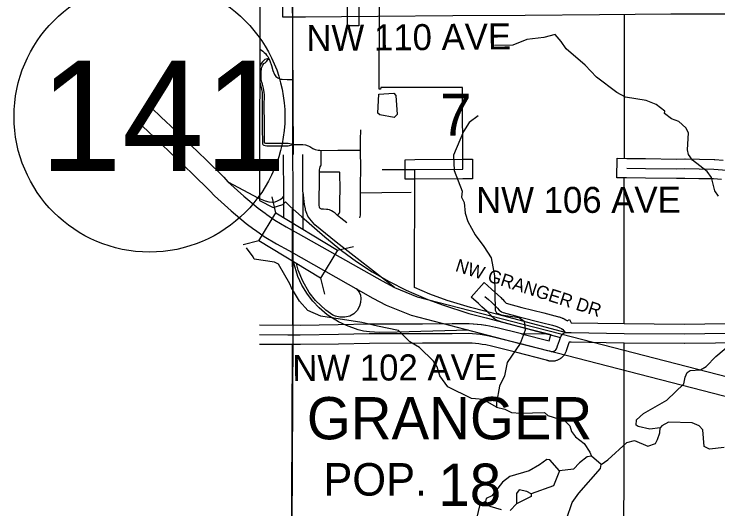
# Model space of a CAD drawing. Extents: x -1403959 to 81668, y -1400582 to 11018.
# Drawn here: x 6135.6 to 6345.3, y 9255.5 to 9402.8 of the extents above; entities that cross this region are included whole.
import ezdxf

# ---------------------------------------------------------------- set-up
doc = ezdxf.new("R2010")
doc.units = 0
for name, color, linetype in [('tdCiCityStreetTxt', 7, 'Continuous'), ('tdCiCoBndryTxt', 7, 'Continuous'), ('tdCiCorpBndryTxt', 7, 'Continuous'), ('tdCiMapCityName', 7, 'Continuous'), ('tdCiMapFrame', 7, 'Continuous'), ('tdCiRRCL', 7, 'Continuous'), ('tdCiSectLine', 7, 'Continuous'), ('tdCiSectTwpRng', 7, 'Continuous'), ('tdCoCityStreetMajor', 7, 'Continuous'), ('tdCoCityStreetMinor', 7, 'Continuous'), ('tdCoClipBndry', 7, 'Continuous'), ('tdCoDivCarto', 7, 'Continuous'), ('tdCoIntCL', 7, 'Continuous'), ('tdCoSecRteCL', 7, 'Continuous'), ('tdCoSectLinePart', 7, 'Continuous'), ('tdCoSectNmbr', 7, 'Continuous'), ('tdCoShieldCoRte', 7, 'Continuous'), ('tdCoShieldCoRteHrd', 7, 'Continuous'), ('tdCoSurfAsphalt', 7, 'Continuous'), ('tdCoSurfBitum', 7, 'Continuous')]:
    doc.layers.add(name, color=color, linetype=linetype)

msp = doc.modelspace()

# ---------------------------------------------------------------- linework, layer by layer
at = {"layer": 'tdCiCityStreetTxt'}
for p, q in [((6213.62, 9343.61), (6212.46, 9348.35)), ((6208.57, 9335.28), (6213.62, 9343.61)), ((6213.62, 9343.61), (6231.96, 9332.49)), ((6208.57, 9335.28), (6203.84, 9334.12)), ((6226.91, 9324.16), (6208.57, 9335.28)), ((6208.57, 9335.28), (6208.57, 9335.28)), ((6231.96, 9332.49), (6236.7, 9333.65)), ((6231.96, 9332.49), (6226.91, 9324.16)), ((6226.91, 9324.16), (6228.07, 9319.42))]:
    msp.add_line(p, q, dxfattribs=at)
at = {"layer": 'tdCiCoBndryTxt'}
for points in [[(6339.67, 9356.69), (6339.67, 9356.69), (6344.07, 9356.61), (6346.6, 9356.39), (6349.31, 9356.23), (6354.12, 9356.2), (6362.21, 9356.1), (6365.11, 9356.29), (6365.94, 9356.34)], [(6298.4, 9306.53), (6298.56, 9306.95), (6299.06, 9307.64), (6299.74, 9307.97)], [(6299.74, 9307.97), (6301.59, 9308.02), (6317.33, 9307.76), (6335.22, 9307.64), (6353.75, 9307.88), (6365.08, 9307.76), (6365.85, 9307.83)], [(6297.78, 9304.85), (6298.05, 9305.63), (6298.4, 9306.53)]]:
    msp.add_lwpolyline(points, dxfattribs=at)
at = {"layer": 'tdCiCorpBndryTxt'}
msp.add_lwpolyline([(6280.8, 9314.19), (6281.34, 9314), (6286.09, 9312.69), (6292.71, 9311.02), (6295.97, 9310.2), (6296.97, 9309.91), (6297.78, 9309.62), (6298.18, 9309.43), (6298.63, 9309.21), (6299.05, 9308.86), (6299.4, 9308.5), (6299.74, 9307.97)], dxfattribs=at)
at = {"layer": 'tdCiMapCityName'}
for points in [[(6254.99, 9356.56), (6269.26, 9356.66)], [(6318.12, 9356.94), (6323.69, 9356.86), (6332.97, 9356.71), (6335.44, 9356.78), (6339.67, 9356.69)]]:
    msp.add_lwpolyline(points, dxfattribs=at)
at = {"layer": 'tdCiMapFrame'}
for points in [[(6275.88, 9318.75), (6276.9, 9317.83), (6277.81, 9317), (6278.54, 9316.34), (6279, 9315.87), (6279.62, 9315.24), (6280.13, 9314.7), (6280.43, 9314.44), (6280.8, 9314.19)], [(6218.65, 9307.34), (6220.86, 9307.33), (6232.24, 9307.47), (6241.43, 9307.67), (6257.27, 9307.74), (6266.12, 9307.76), (6271.08, 9307.78), (6272.2, 9307.74), (6273.32, 9307.65), (6274.44, 9307.52), (6275.55, 9307.35), (6276.66, 9307.14), (6278.45, 9306.76), (6286.06, 9304.85), (6294.5, 9302.7), (6295.12, 9302.54), (6295.36, 9302.43), (6295.62, 9302.37), (6295.88, 9302.35), (6296.14, 9302.38), (6296.39, 9302.45), (6296.63, 9302.56), (6296.84, 9302.71), (6297.03, 9302.9), (6297.18, 9303.11), (6297.29, 9303.35), (6297.51, 9304.08), (6297.78, 9304.85)], [(6208.71, 9307.38), (6217.19, 9307.35)], [(6217.19, 9307.35), (6218.65, 9307.34)]]:
    msp.add_lwpolyline(points, dxfattribs=at)
at = {"layer": 'tdCiRRCL'}
msp.add_line((6208.84, 9452.88), (6208.75, 9347.31), dxfattribs=at)
for points in [[(6208.75, 9347.31), (6212.79, 9345.2), (6215.68, 9346.09), (6216.49, 9346.9), (6217.91, 9345.49), (6221.26, 9342.49), (6228.17, 9336.51), (6233.11, 9332.44), (6237.61, 9329.15), (6242.27, 9326.11), (6247.36, 9323.17), (6252.42, 9320.62), (6254.73, 9319.62), (6258.91, 9317.83), (6263.26, 9316.24), (6271.11, 9313.71), (6276.22, 9312.37), (6298.4, 9306.53), (6298.56, 9306.95), (6298.81, 9307.3), (6299.07, 9307.65), (6299.74, 9307.97), (6280.14, 9313.23), (6271.57, 9315.48), (6264.67, 9317.55), (6259.46, 9319.46), (6254.87, 9321.44), (6254.99, 9356.56), (6269.26, 9356.66), (6269.22, 9380.92), (6244.82, 9380.94), (6244.77, 9380.41), (6244.35, 9380.41), (6244.46, 9404.95)], [(6238.31, 9404.9), (6238.29, 9399.31), (6234.9, 9399.29), (6234.92, 9404.87)]]:
    msp.add_lwpolyline(points, dxfattribs=at)
at = {"layer": 'tdCiSectLine'}
for points in [[(6348.3, 9402.76), (6331.22, 9402.7), (6310.03, 9402.55), (6287.9, 9402.36), (6287.89, 9402.36), (6266.31, 9402.2), (6266.31, 9402.2), (6243.96, 9402.04), (6233.15, 9401.95), (6233.14, 9401.95), (6222.39, 9401.87), (6222.38, 9401.87), (6218.56, 9401.86), (6215.66, 9401.85), (6215.64, 9407.65)], [(6346.34, 9353.5), (6343.92, 9353.71), (6339.63, 9353.78), (6339.61, 9353.78), (6335.45, 9353.88), (6333.04, 9353.81), (6332.97, 9353.81), (6332.92, 9353.81), (6323.65, 9353.96), (6318.07, 9354.04), (6315.17, 9354.08), (6315.26, 9359.88), (6318.16, 9359.84), (6323.74, 9359.76), (6323.74, 9359.76), (6332.95, 9359.61), (6335.36, 9359.68), (6335.44, 9359.68), (6335.5, 9359.68), (6339.73, 9359.59), (6344.11, 9359.52), (6344.26, 9359.51), (6344.32, 9359.5), (6346.81, 9359.28)], [(6252.11, 9353.63), (6252.07, 9359.44), (6254.97, 9359.46), (6269.24, 9359.57), (6272.14, 9359.59), (6272.19, 9353.78), (6269.29, 9353.76), (6255.01, 9353.66), (6252.11, 9353.63)], [(6208.71, 9310.28), (6220.85, 9310.23), (6232.19, 9310.38), (6241.37, 9310.57), (6241.41, 9310.57), (6257.25, 9310.64), (6257.26, 9310.64), (6266.1, 9310.66), (6271.06, 9310.69), (6271.08, 9310.69), (6271.2, 9310.68), (6272.32, 9310.64), (6272.39, 9310.63), (6272.43, 9310.63), (6273.55, 9310.54), (6273.66, 9310.53), (6274.77, 9310.4), (6274.82, 9310.4), (6274.88, 9310.39), (6275.99, 9310.22), (6276.09, 9310.2), (6277.2, 9309.99), (6277.22, 9309.99), (6277.26, 9309.98), (6279.05, 9309.6), (6279.15, 9309.57), (6286.76, 9307.67), (6286.77, 9307.66), (6294.96, 9305.58), (6295.31, 9306.59), (6295.34, 9306.68), (6295.58, 9307.29), (6295.21, 9307.4), (6292, 9308.21), (6285.38, 9309.88), (6285.34, 9309.89), (6285.33, 9309.9), (6280.57, 9311.2), (6280.41, 9311.25), (6280.37, 9311.26), (6279.83, 9311.45), (6279.69, 9311.51), (6279.52, 9311.59), (6279.35, 9311.68), (6279.19, 9311.78), (6279.14, 9311.81), (6278.78, 9312.06), (6278.67, 9312.14), (6278.56, 9312.22), (6278.26, 9312.48), (6278.22, 9312.52), (6278.08, 9312.65), (6278.02, 9312.71), (6277.53, 9313.23), (6276.94, 9313.84), (6276.54, 9314.24), (6274.95, 9315.68), (6273.94, 9316.6), (6271.79, 9318.55), (6275.68, 9322.85), (6277.83, 9320.9), (6278.85, 9319.98), (6278.86, 9319.97), (6280.5, 9318.48), (6280.59, 9318.39), (6281.05, 9317.93), (6281.08, 9317.9), (6281.7, 9317.26), (6281.73, 9317.23), (6282.13, 9316.81), (6282.15, 9316.79), (6282.21, 9316.77), (6286.83, 9315.5), (6293.42, 9313.84), (6293.42, 9313.84), (6296.68, 9313.01), (6296.72, 9313), (6296.77, 9312.99), (6297.77, 9312.7), (6297.9, 9312.66), (6297.94, 9312.65), (6298.75, 9312.36), (6298.89, 9312.31), (6299.04, 9312.24), (6299.44, 9312.05), (6299.46, 9312.04), (6299.48, 9312.03), (6299.92, 9311.81), (6300.08, 9311.72), (6300.24, 9311.62), (6300.39, 9311.51), (6300.39, 9311.51), (6301.09, 9311.85), (6301.53, 9310.92), (6301.59, 9310.92), (6301.63, 9310.92), (6317.36, 9310.66), (6335.21, 9310.54), (6353.72, 9310.78)], [(6353.76, 9304.98), (6335.26, 9304.74), (6335.22, 9304.74), (6335.2, 9304.74), (6317.31, 9304.86), (6317.28, 9304.86), (6301.6, 9305.12), (6300.95, 9305.1), (6300.77, 9304.63), (6300.27, 9303.2), (6300.08, 9302.53), (6300.04, 9302.41), (6299.97, 9302.24), (6299.91, 9302.1), (6299.8, 9301.87), (6299.78, 9301.83), (6299.69, 9301.66), (6299.59, 9301.5), (6299.55, 9301.44), (6299.4, 9301.22), (6299.33, 9301.13), (6299.21, 9300.98), (6299.08, 9300.84), (6298.9, 9300.66), (6298.76, 9300.53), (6298.61, 9300.41), (6298.52, 9300.34), (6298.3, 9300.19), (6298.24, 9300.15), (6298.08, 9300.05), (6297.91, 9299.96), (6297.87, 9299.94), (6297.64, 9299.83), (6297.5, 9299.77), (6297.32, 9299.7), (6297.17, 9299.65), (6296.92, 9299.58), (6296.89, 9299.57), (6296.71, 9299.53), (6296.52, 9299.5), (6296.43, 9299.49), (6296.17, 9299.46), (6296.07, 9299.45), (6295.88, 9299.45), (6295.69, 9299.45), (6295.67, 9299.46), (6295.41, 9299.47), (6295.24, 9299.49), (6295.05, 9299.52), (6294.92, 9299.55), (6294.67, 9299.61), (6294.61, 9299.63), (6294.43, 9299.68), (6294.25, 9299.75), (6294.2, 9299.77), (6294.16, 9299.79), (6293.77, 9299.9), (6285.35, 9302.04), (6277.79, 9303.93), (6276.09, 9304.3), (6275.06, 9304.49), (6274.06, 9304.64), (6273.04, 9304.76), (6272.02, 9304.84), (6271.02, 9304.88), (6266.13, 9304.86), (6266.12, 9304.86), (6257.28, 9304.83), (6241.46, 9304.76), (6232.3, 9304.57), (6232.28, 9304.57), (6220.9, 9304.43), (6220.86, 9304.43), (6220.85, 9304.43), (6208.71, 9304.48)]]:
    msp.add_lwpolyline(points, dxfattribs=at)
at = {"layer": 'tdCiSectTwpRng'}
for points in [[(6208.79, 9392.35), (6208.87, 9392.3), (6209.32, 9392.03), (6209.75, 9391.71), (6210.15, 9391.37), (6210.52, 9391), (6210.86, 9390.59), (6211.17, 9390.16), (6211.44, 9389.71), (6211.52, 9389.54), (6211.81, 9388.85), (6212.26, 9387.42), (6212.7, 9386.02), (6213.21, 9384.78), (6213.4, 9384.5), (6213.63, 9384.24), (6213.88, 9384.01), (6214.16, 9383.81), (6214.46, 9383.65), (6214.78, 9383.53), (6215.11, 9383.44), (6215.45, 9383.4), (6217.01, 9383.33), (6218.61, 9383.35)], [(6211.52, 9389.54), (6210.27, 9389.24), (6209.65, 9388.6), (6209.27, 9388.06), (6209.09, 9387.71), (6208.88, 9387.31), (6208.78, 9387.03)], [(6210.18, 9370.45), (6210.16, 9375.29), (6210.2, 9378.79), (6210.13, 9379.48), (6209.96, 9380.73), (6209.63, 9381.91), (6209.45, 9382.48), (6209.27, 9383.33), (6209.2, 9384.05), (6209.19, 9385.61), (6209.28, 9386.46), (6209.44, 9387.02), (6209.7, 9387.6), (6210.03, 9388.02), (6210.44, 9388.29), (6210.86, 9388.61), (6211.52, 9389.54)], [(6208.78, 9382.44), (6209.22, 9380.89), (6209.37, 9380.33), (6209.52, 9379.53), (6209.53, 9378.69), (6209.5, 9374.57), (6209.55, 9370.44)], [(6209.55, 9370.44), (6209.57, 9368.49), (6209.58, 9364.8), (6209.59, 9364.4), (6209.63, 9364.17), (6209.71, 9363.99), (6209.83, 9363.89), (6210.01, 9363.77), (6210.43, 9363.66), (6210.91, 9363.59), (6211.57, 9363.57), (6217.3, 9363.61), (6218.74, 9363.99)], [(6218.74, 9363.99), (6217.3, 9364.26), (6212.58, 9364.25), (6211.51, 9364.23), (6211.05, 9364.21), (6210.65, 9364.21), (6210.36, 9364.35), (6210.25, 9364.64), (6210.24, 9364.93), (6210.2, 9367.55), (6210.18, 9370.45)], [(6238.6, 9342.17), (6238.78, 9342.9), (6238.8, 9346.11), (6238.83, 9349.58), (6238.83, 9351.86), (6238.87, 9356.79), (6238.83, 9362.31), (6238.81, 9365.35), (6238.86, 9368.28)], [(6238.86, 9368.28), (6238.86, 9368.28)], [(6218.74, 9363.99), (6220.65, 9363.95), (6221.67, 9363.96), (6222.46, 9363.84), (6223.19, 9363.55), (6223.69, 9363.32), (6224.61, 9362.75), (6225.31, 9362.43), (6226.18, 9362.26), (6226.71, 9362.24), (6227.13, 9362.22), (6227.16, 9362.22), (6232.07, 9362.31), (6237.32, 9362.31), (6238.83, 9362.31)], [(6227.07, 9358.14), (6227.13, 9362.22)], [(6227.13, 9362.22), (6227.13, 9362.22)], [(6226.79, 9344.94), (6226.69, 9345.08), (6226.61, 9345.23), (6226.55, 9345.38), (6226.54, 9345.83), (6226.53, 9347.42), (6226.57, 9353.02), (6226.57, 9355.1), (6226.6, 9355.8), (6226.61, 9356.43), (6226.68, 9356.86), (6226.83, 9357.27), (6226.97, 9357.63), (6227.06, 9357.95)], [(6227.06, 9357.95), (6227.07, 9358), (6227.07, 9358.14)], [(6226.6, 9355.8), (6229.57, 9355.78), (6232.11, 9355.83), (6232.43, 9355.83), (6232.53, 9355.77)], [(6231.99, 9342.83), (6232.46, 9343.44), (6232.64, 9343.92), (6232.68, 9344.46), (6232.68, 9346.2), (6232.71, 9351.68), (6232.7, 9354.43), (6232.7, 9354.86), (6232.68, 9355.31), (6232.63, 9355.6), (6232.57, 9355.74)], [(6245.28, 9356.49), (6254.99, 9356.56)], [(6238.83, 9349.58), (6245.13, 9349.66), (6253.87, 9349.73)], [(6234.7, 9340.63), (6232.94, 9342.04), (6231.99, 9342.83), (6231.22, 9343.51), (6230.68, 9343.92), (6230.2, 9344.24), (6229.57, 9344.49), (6229.11, 9344.59), (6228.66, 9344.64), (6227.82, 9344.67), (6227.42, 9344.68), (6227.19, 9344.72), (6226.96, 9344.8), (6226.79, 9344.94)]]:
    msp.add_lwpolyline(points, dxfattribs=at)
at = {"layer": 'tdCoCityStreetMajor'}
for points in [[(6317.39, 9359.86), (6317.45, 9402.6)], [(6317.32, 9310.68), (6317.38, 9354.05)], [(6218.58, 9344.86), (6218.61, 9310.24)], [(6286.72, 9307.65), (6293.99, 9307.69)], [(6218.6, 9304.44), (6218.13, 9211.25)], [(6317.27, 9211.34), (6317.32, 9304.88)]]:
    msp.add_lwpolyline(points, dxfattribs=at)
at = {"layer": 'tdCoCityStreetMinor'}
for points in [[(6218.61, 9310.24), (6218.58, 9344.86)], [(6218.14, 9115.55), (6218.13, 9211.25), (6218.6, 9304.44)]]:
    msp.add_lwpolyline(points, dxfattribs=at)
at = {"layer": 'tdCoClipBndry'}
msp.add_lwpolyline([(6778.71, 10085.37), (6705.52, 10085.58), (6607.92, 10086.06), (6510.34, 10086.5), (6412.84, 10087.26), (6315.56, 10087.31), (6215.78, 10087.65), (6215.21, 10012.23), (6215.81, 9994.41), (6217.04, 9970.57), (6217.41, 9896.62), (6217.06, 9848.03), (6217.62, 9799.5), (6216.78, 9702.88), (6218.33, 9606.68), (6218.57, 9510.16), (6218.52, 9404.76), (6218.61, 9307.34), (6218.13, 9211.25), (6218.14, 9113.22), (6218.14, 9016.46), (6218.02, 8919.84), (6217.44, 8816.34), (6216.99, 8719.3)], dxfattribs=at)
at = {"layer": 'tdCoDivCarto'}
for points in [[(6176.57, 9374.83), (6179.4, 9372.12), (6183.67, 9368.17), (6192.8, 9359.37), (6198.06, 9354.21), (6199.34, 9352.88), (6204.07, 9348.6), (6208.3, 9345.04), (6210.39, 9343.54), (6210.91, 9343.16)], [(6172.57, 9370.63), (6175.43, 9367.9), (6179.68, 9363.96), (6188.75, 9355.21), (6193.94, 9350.12), (6195.3, 9348.71), (6200.25, 9344.22), (6204.74, 9340.45), (6207.03, 9338.8), (6207.52, 9338.45)], [(6215.99, 9342.18), (6215.94, 9348.58), (6215.84, 9360.92)], [(6221.78, 9338.66), (6221.64, 9360.98)], [(6210.91, 9343.16), (6213.31, 9341.44), (6216.63, 9339.43), (6220.29, 9337.52), (6245.26, 9323.35), (6248.94, 9321.36), (6255.72, 9318.67), (6287.26, 9310.48), (6298.49, 9307.66), (6360.8, 9291.59), (6380.46, 9286.54), (6385.69, 9284.96), (6388.03, 9284.17), (6390.87, 9282.89), (6395.32, 9280.4), (6397.51, 9278.98), (6403.14, 9273.65), (6405.09, 9271.28), (6407.64, 9267.35), (6408.76, 9265.21)], [(6207.52, 9338.45), (6210.11, 9336.59), (6213.78, 9334.37), (6217.44, 9332.46), (6242.47, 9318.27), (6246.44, 9316.12), (6253.94, 9313.14), (6285.82, 9304.86), (6297.01, 9302.05), (6359.33, 9285.97), (6378.93, 9280.94), (6383.88, 9279.45), (6385.9, 9278.76), (6388.27, 9277.69), (6392.32, 9275.43), (6394.46, 9274.02), (6398.89, 9269.68), (6400.4, 9267.85), (6402.63, 9264.42), (6403.41, 9262.91)]]:
    msp.add_lwpolyline(points, dxfattribs=at)
at = {"layer": 'tdCoIntCL'}
for points in [[(6199.34, 9352.88), (6208.43, 9347.96), (6210.44, 9347.19), (6211.46, 9346.91), (6212.49, 9346.77), (6213.36, 9346.89), (6214.12, 9347.19), (6214.91, 9347.57), (6215.32, 9347.84), (6215.58, 9348.07), (6215.94, 9348.58)], [(6248.94, 9321.36), (6231.55, 9334.86), (6225.23, 9340.03), (6223.69, 9341.81), (6223.17, 9342.64), (6222.83, 9343.43), (6222.47, 9344.43), (6222.38, 9344.78), (6222.15, 9346.09), (6221.71, 9349.82)], [(6271, 9308.71), (6249.77, 9308.12), (6244.49, 9308.06), (6241.51, 9308.19), (6239.74, 9308.45), (6238.13, 9308.83), (6234.65, 9310.06), (6232.21, 9311.21), (6228.91, 9313.27), (6226.49, 9315.34), (6224.62, 9317.31), (6223, 9319.4), (6221.3, 9322.13), (6220.12, 9324.68), (6218.81, 9329.07)], [(6237.52, 9321.07), (6238.38, 9320.06), (6238.77, 9319.1), (6238.92, 9318.08), (6238.83, 9316.97), (6238.48, 9315.81), (6237.79, 9314.57), (6236.78, 9313.61), (6235.64, 9312.89), (6234.13, 9312.56), (6232.65, 9312.53), (6231.32, 9312.83), (6230.58, 9313.13), (6228.46, 9314.61), (6225.45, 9317.56), (6223.52, 9319.95), (6221.6, 9323.27), (6220.23, 9326.59), (6219.71, 9328.53)]]:
    msp.add_lwpolyline(points, dxfattribs=at)
at = {"layer": 'tdCoSecRteCL'}
msp.add_lwpolyline([(6218.5, 9411.49), (6218.74, 9360.95)], dxfattribs=at)
at = {"layer": 'tdCoSurfAsphalt'}
msp.add_circle((6175.96, 9372.27), 40.33, dxfattribs=at)
at = {"layer": 'tdCoSurfBitum'}
for points in [[(6345.43, 9348.59), (6344.37, 9350.12), (6343.31, 9354.1), (6342.1, 9355.93), (6337.68, 9359.31), (6336.47, 9360.99), (6336.16, 9362.37), (6336.49, 9367.41), (6335.73, 9368.94), (6333.6, 9370.78), (6331.46, 9371.55), (6329.33, 9373.23), (6329.49, 9373.84), (6326.9, 9375.84), (6323.85, 9377.07), (6317.74, 9378.01), (6315.15, 9379.39), (6309.06, 9384), (6305.71, 9387.52), (6300.08, 9392.43), (6298.56, 9394.57), (6296.74, 9396.71), (6293.38, 9395.81), (6288.33, 9395.22), (6284.21, 9393.56), (6278.71, 9393.42)], [(6248.85, 9372.01), (6244.58, 9372.79), (6243.97, 9373.25), (6244.3, 9378.9), (6248.73, 9379.19), (6249.34, 9378.57), (6249.77, 9372.92), (6248.85, 9372.01)], [(6273.9, 9372.53), (6271.14, 9370.55), (6269.45, 9367.81), (6266.53, 9360.8), (6266.66, 9356.22), (6269.09, 9350.1), (6268.93, 9348.27), (6269.68, 9346.74), (6269.98, 9343.54), (6270.73, 9341.09), (6273.01, 9337.11), (6275.59, 9333.59), (6277.71, 9330.23), (6278.76, 9324.88), (6278.88, 9314.65), (6279.33, 9313.89), (6280.7, 9313.27), (6286.04, 9312.49), (6287.57, 9311.41), (6287.86, 9308.66), (6286.32, 9304.7), (6282.48, 9299.07), (6281.71, 9295.1), (6280.17, 9292.05), (6279.27, 9287.06), (6279.32, 9285.84), (6281.84, 9285.17), (6283.77, 9284.21), (6286.44, 9283.98), (6293.58, 9284.22), (6294.64, 9283.3), (6299.68, 9281.75), (6301.2, 9280.22), (6301.65, 9278.54), (6302.87, 9277.01), (6305.46, 9275.01), (6307.13, 9272.41), (6307.58, 9271.19), (6306.36, 9271.04), (6304.06, 9269.22), (6302.22, 9267.39), (6298.1, 9266.8), (6296.25, 9262.37), (6289.68, 9259.96), (6289.67, 9259.19), (6285.24, 9257.07), (6283.4, 9255.09)], [(6279.32, 9285.84), (6275.39, 9288.06), (6271.91, 9288.36), (6264.79, 9291.85), (6262.41, 9295.11), (6261.62, 9297.77), (6260.55, 9299.45), (6256.41, 9303.59), (6253.49, 9305.28), (6250.12, 9308.65), (6243.83, 9309.9), (6239.23, 9310.98), (6226.95, 9312.86), (6223.11, 9314.56), (6220.66, 9317.31), (6218.21, 9321.29), (6217.75, 9322.51), (6214.38, 9328.33), (6213.15, 9328.94), (6207.17, 9329.88), (6206.86, 9330.49), (6204.81, 9333.2)], [(6347.14, 9273.79), (6342.71, 9273.34), (6341.19, 9274.11), (6340.75, 9279), (6339.68, 9280.23), (6337.55, 9281.15), (6330.52, 9281.33), (6328.53, 9280.27), (6328.07, 9279.66), (6325.02, 9279.21), (6321.51, 9279.99), (6320.9, 9280.45), (6321.06, 9281.98), (6323.05, 9283.95), (6330.09, 9287.9), (6335.14, 9292.76), (6335.46, 9294.74), (6336.07, 9296.12), (6336.99, 9296.72), (6340.04, 9296.86), (6341.73, 9297.93), (6344.64, 9300.82), (6350.15, 9305.53)], [(6300.19, 9252.44), (6301.88, 9257.47), (6303.88, 9260.21), (6310.32, 9267.51), (6310.47, 9268.73), (6312.46, 9270.1), (6318.13, 9275.27), (6320.43, 9275.87), (6324.39, 9274.18), (6326.68, 9274.93), (6327.3, 9276.15), (6327.92, 9278.13), (6328.07, 9279.66)], [(6298.1, 9266.8), (6295.21, 9270.16), (6294.29, 9270.17), (6292.15, 9268.65), (6289.09, 9266.83), (6283.28, 9265.17), (6281.14, 9263.5), (6277.92, 9259.39), (6276.23, 9258.63), (6276.08, 9257.72)], [(6310.47, 9268.73), (6307.58, 9271.19)], [(6286.02, 9261.19), (6285.25, 9260.13), (6285.24, 9257.07)], [(6289.68, 9259.96), (6288.3, 9260.73), (6286.02, 9261.19)], [(6280.8, 9255.26), (6277.45, 9256.19), (6276.08, 9257.72), (6274.39, 9256.81), (6273.31, 9252.69)]]:
    msp.add_lwpolyline(points, dxfattribs=at)

# ---------------------------------------------------------------- texts
at = {"layer": 'tdCoSectLinePart'}
for s, height, p in [('7', 12.57, (6262.56, 9366.54)), ('18', 12.575, (6262, 9256.42))]:
    msp.add_text(s, height=height, rotation=359.9883, dxfattribs=at).set_placement(p)
at = {"layer": 'tdCoSectNmbr'}
for s, height, rotation, p in [('NW 110 AVE', 7.738, 0.5095, (6222.74, 9391.74)), ('NW 106 AVE', 7.738, 0.0924, (6273.25, 9343.55)), ('NW GRANGER DR', 3.8691, 342.2383, (6266.81, 9326.35)), ('NW 102 AVE', 7.738, 0.2817, (6218.51, 9293.58))]:
    msp.add_text(s, height=height, rotation=rotation, dxfattribs=at).set_placement(p)
at = {"layer": 'tdCoShieldCoRte'}
msp.add_text('POP.', height=9.673, rotation=359.9944, dxfattribs=at).set_placement((6227.74, 9259.48))
at = {"layer": 'tdCoShieldCoRteHrd'}
msp.add_text('GRANGER', height=12.575, dxfattribs=at).set_placement((6222.83, 9276.22))
at = {"layer": 'tdCoSurfAsphalt'}
msp.add_text('141', height=32.887, dxfattribs=at).set_placement((6143.29, 9356.04))

doc.saveas('drawing.dxf')
